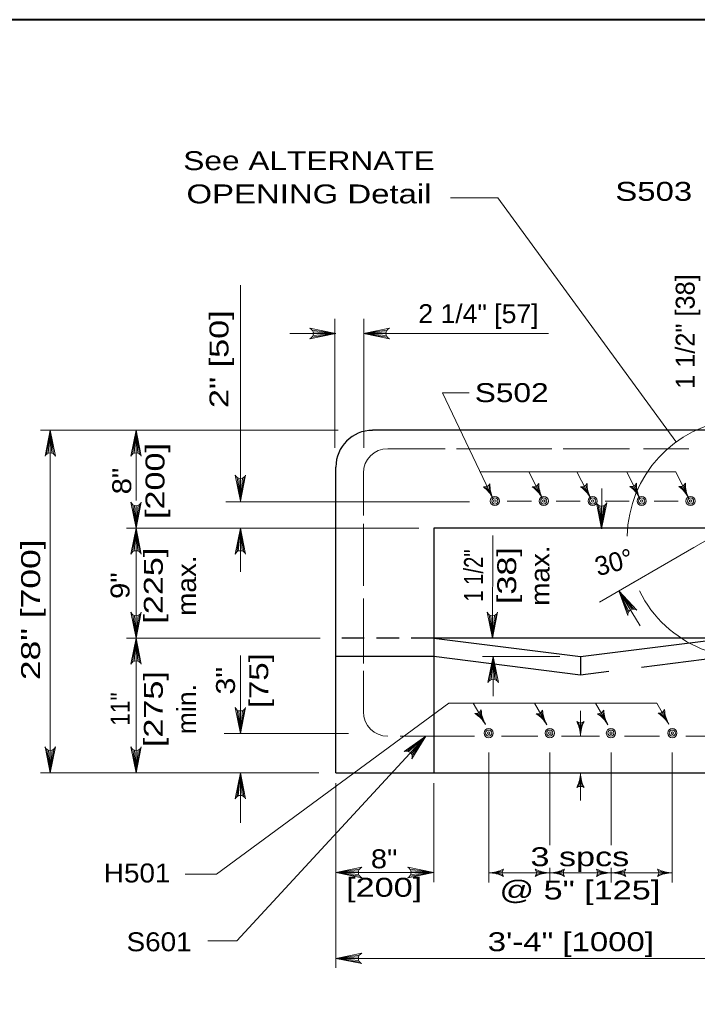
# Model space of a CAD drawing. Extents: x 758.3 to 792.3, y 849.7 to 893.7.
# Drawn here: x 775.35 to 780.94, y 863.16 to 871.19 of the extents above; entities that cross this region are included whole.
import ezdxf
from ezdxf.enums import TextEntityAlignment as Align

# ---------------------------------------------------------------- set-up
doc = ezdxf.new("R2010")
doc.units = 0
doc.header["$LTSCALE"] = 0.062
doc.linetypes.add('MEDIUM_DASHED', pattern=[4.5, 3, -1.5])
doc.layers.add('1', color=7, linetype='Continuous', lineweight=13)

msp = doc.modelspace()

# ---------------------------------------------------------------- linework, layer by layer
at = {"layer": '1', "lineweight": 25}
for p, q in [((760.3205, 871.18817), (791.8205, 871.18817)), ((781.58392, 867.80392), (778.25792, 867.80392)), ((777.95558, 864.98217), (777.95558, 867.50158)), ((781.18075, 866.99767), (778.76192, 866.99767)), ((778.76192, 865.93958), (777.95533, 865.93958)), ((779.97133, 865.78842), (778.76192, 865.93958)), ((779.97133, 865.93958), (779.97133, 865.78842)), ((781.18075, 865.93958), (780.47375, 865.85117)), ((780.20467, 865.81758), (779.97133, 865.78842)), ((777.95558, 864.98217), (781.987, 864.98217))]:
    msp.add_line(p, q, dxfattribs=at)
at = {"layer": '1'}
for p, q in [((777.16925, 867.22175), (777.16925, 868.99883)), ((777.946, 867.65858), (777.946, 868.72225)), ((778.18575, 867.65858), (778.18575, 868.72225)), ((777.76167, 868.62858), (777.95558, 868.6015)), ((777.76825, 868.61517), (777.95558, 868.6015)), ((778.37625, 868.62858), (778.18233, 868.6015)), ((778.36967, 868.61517), (778.18233, 868.6015)), ((777.57658, 868.6015), (777.95558, 868.6015)), ((777.75942, 868.5715), (777.95558, 868.6015)), ((777.76683, 868.58408), (777.95558, 868.6015)), ((777.77025, 868.6015), (777.95558, 868.6015)), ((779.70858, 868.6015), (778.18233, 868.6015)), ((778.36767, 868.6015), (778.18233, 868.6015)), ((778.37117, 868.58408), (778.18233, 868.6015)), ((778.37858, 868.5715), (778.18233, 868.6015)), ((779.25042, 867.24225), (778.83492, 868.114)), ((778.83492, 868.114), (779.05475, 868.114)), ((777.97483, 867.80392), (775.523, 867.80392)), ((775.57167, 867.60775), (775.60167, 867.80392)), ((775.58425, 867.61517), (775.60167, 867.80392)), ((775.60167, 867.61858), (775.60167, 867.80392)), ((775.61542, 867.61658), (775.60167, 867.80392)), ((775.62883, 867.61), (775.60167, 867.80392)), ((775.60167, 864.98217), (775.60167, 867.80392)), ((776.27967, 867.60767), (776.30967, 867.80392)), ((776.29225, 867.61517), (776.30967, 867.80392)), ((776.30967, 867.22517), (776.30967, 867.80392)), ((776.30967, 867.61858), (776.30967, 867.80392)), ((776.32342, 867.61658), (776.30967, 867.80392)), ((776.33683, 867.61), (776.30967, 867.80392)), ((778.85583, 867.65275), (778.38392, 867.65275)), ((779.73592, 867.65275), (778.94967, 867.65275)), ((780.37625, 867.65275), (779.82742, 867.65275)), ((780.86417, 867.65275), (780.49058, 867.65275)), ((777.14217, 867.41558), (777.16925, 867.22175)), ((777.15558, 867.409), (777.16925, 867.22175)), ((777.19925, 867.41792), (777.16925, 867.22175)), ((777.18667, 867.4105), (777.16925, 867.22175)), ((777.16925, 867.407), (777.16925, 867.22175)), ((778.18233, 867.10258), (778.18233, 867.45117)), ((780.75642, 867.46117), (779.14808, 867.46117)), ((779.657, 867.24567), (779.5445, 867.46117)), ((780.055, 867.24567), (779.9425, 867.46117)), ((780.45983, 867.24567), (780.35333, 867.46117)), ((780.863, 867.24567), (780.75642, 867.46117)), ((780.14867, 866.99333), (780.14867, 867.32417)), ((776.2825, 867.19158), (776.30967, 866.99767)), ((776.296, 867.185), (776.30967, 866.99767)), ((776.33967, 867.19383), (776.30967, 866.99767)), ((776.32708, 867.18642), (776.30967, 866.99767)), ((776.30967, 867.183), (776.30967, 866.99767)), ((779.05733, 867.21542), (777.04842, 867.21542)), ((779.36783, 867.22175), (779.567, 867.22175)), ((779.77092, 867.22175), (779.97008, 867.22175)), ((780.11833, 867.18742), (780.14542, 866.9935)), ((780.13175, 867.18083), (780.14542, 866.9935)), ((780.17542, 867.18967), (780.14542, 866.9935)), ((780.16283, 867.18225), (780.14542, 866.9935)), ((780.14542, 867.17883), (780.14542, 866.9935)), ((780.17408, 867.22175), (780.37325, 867.22175)), ((780.57725, 867.22175), (780.77642, 867.22175)), ((778.18233, 866.52325), (778.18233, 867.034)), ((778.63983, 866.99767), (776.231, 866.99767)), ((776.27967, 866.8015), (776.30967, 866.99767)), ((776.29225, 866.80892), (776.30967, 866.99767)), ((776.30967, 866.81233), (776.30967, 866.99767)), ((776.32342, 866.81033), (776.30967, 866.99767)), ((776.33683, 866.80383), (776.30967, 866.99767)), ((777.13933, 866.8015), (777.16925, 866.99767)), ((777.15183, 866.80892), (777.16925, 866.99767)), ((777.16925, 866.81233), (777.16925, 866.99767)), ((777.183, 866.81033), (777.16925, 866.99767)), ((777.19642, 866.80383), (777.16925, 866.99767)), ((777.16925, 866.63708), (777.16925, 866.99767)), ((779.2455, 866.09075), (779.24933, 866.93642)), ((781.1055, 866.95425), (780.3815, 866.53625)), ((780.9065, 866.83942), (780.12708, 866.38942)), ((780.38408, 866.32442), (780.2865, 866.482)), ((780.37108, 866.31233), (780.2865, 866.482)), ((780.36425, 866.29942), (780.2865, 866.482)), ((780.39675, 866.32992), (780.2865, 866.482)), ((780.41167, 866.33142), (780.2865, 866.482)), ((780.28717, 866.48133), (780.46225, 866.19467)), ((778.18233, 865.883), (778.18233, 866.41975)), ((776.2825, 866.28458), (776.30967, 866.09075)), ((776.33967, 866.28692), (776.30967, 866.09075)), ((779.21833, 866.28458), (779.2455, 866.09075)), ((779.2755, 866.28692), (779.2455, 866.09075)), ((776.296, 866.278), (776.30967, 866.09075)), ((776.32708, 866.2795), (776.30967, 866.09075)), ((776.30967, 866.276), (776.30967, 866.09075)), ((779.23175, 866.278), (779.2455, 866.09075)), ((779.26292, 866.2795), (779.2455, 866.09075)), ((779.2455, 866.276), (779.2455, 866.09075)), ((777.8265, 866.09075), (776.231, 866.09075)), ((776.27967, 865.8945), (776.30967, 866.09075)), ((776.29225, 865.90192), (776.30967, 866.09075)), ((776.30967, 865.90542), (776.30967, 866.09075)), ((776.32342, 865.90342), (776.30967, 866.09075)), ((776.33683, 865.89683), (776.30967, 866.09075)), ((777.16925, 865.30683), (777.16925, 865.95025)), ((779.16425, 865.93958), (779.80258, 865.93958)), ((779.222, 865.74333), (779.252, 865.93958)), ((779.23458, 865.75075), (779.252, 865.93958)), ((779.252, 865.61375), (779.252, 865.93958)), ((779.252, 865.75425), (779.252, 865.93958)), ((779.26567, 865.75225), (779.252, 865.93958)), ((779.27908, 865.74567), (779.252, 865.93958)), ((778.18233, 865.48608), (778.18233, 865.82192)), ((777.14217, 865.50075), (777.16925, 865.30683)), ((777.15558, 865.49417), (777.16925, 865.30683)), ((777.19925, 865.503), (777.16925, 865.30683)), ((777.18667, 865.49558), (777.16925, 865.30683)), ((777.16925, 865.49217), (777.16925, 865.30683)), ((779.18808, 865.38225), (779.08783, 865.55583)), ((779.69358, 865.3795), (779.59175, 865.55583)), ((779.97133, 865.2845), (779.97133, 865.49217)), ((780.19725, 865.37983), (780.09567, 865.55583)), ((780.69867, 865.38417), (780.59958, 865.55583)), ((778.05942, 865.30683), (777.0355, 865.30683)), ((778.696, 865.2845), (777.1395, 863.59783)), ((779.09925, 865.2845), (778.48433, 865.2845)), ((778.54017, 865.16158), (778.696, 865.2845)), ((778.55442, 865.15842), (778.696, 865.2845)), ((778.5695, 865.149), (778.696, 865.2845)), ((778.57817, 865.13825), (778.696, 865.2845)), ((778.58342, 865.12433), (778.696, 865.2845)), ((779.6205, 865.2845), (779.32067, 865.2845)), ((780.12792, 865.2845), (779.81433, 865.2845)), ((780.62158, 865.2845), (780.33333, 865.2845)), ((781.23192, 865.2845), (780.83842, 865.2845)), ((775.5745, 865.17608), (775.60167, 864.98217)), ((775.588, 865.1695), (775.60167, 864.98217)), ((775.63167, 865.17833), (775.60167, 864.98217)), ((775.61908, 865.17092), (775.60167, 864.98217)), ((775.60167, 865.1675), (775.60167, 864.98217)), ((776.2825, 865.17608), (776.30967, 864.98217)), ((776.296, 865.1695), (776.30967, 864.98217)), ((776.33967, 865.17833), (776.30967, 864.98217)), ((776.32708, 865.17092), (776.30967, 864.98217)), ((776.30967, 865.1675), (776.30967, 864.98217)), ((779.21542, 865.15017), (779.21542, 864.08058)), ((779.71933, 865.15017), (779.71933, 864.388)), ((780.22325, 865.15017), (780.22325, 864.388)), ((780.72717, 865.15017), (780.72717, 864.08058)), ((775.523, 864.98217), (777.81458, 864.98217)), ((777.13933, 864.786), (777.16925, 864.98217)), ((777.15183, 864.79342), (777.16925, 864.98217)), ((777.16925, 864.57042), (777.16925, 864.98217)), ((777.16925, 864.79683), (777.16925, 864.98217)), ((777.183, 864.79483), (777.16925, 864.98217)), ((777.19642, 864.78825), (777.16925, 864.98217)), ((779.97133, 864.75383), (779.97133, 864.98217)), ((777.95558, 864.89833), (777.95558, 863.37508)), ((778.76192, 864.89833), (778.76192, 864.08308)), ((777.95558, 864.17858), (777.95558, 864.52392)), ((779.71933, 864.19958), (779.71933, 864.08058)), ((780.22325, 864.19958), (780.22325, 864.08058)), ((776.97192, 864.14817), (776.71483, 864.14817)), ((778.1495, 864.18892), (777.95558, 864.16175)), ((778.14292, 864.1755), (777.95558, 864.16175)), ((777.95558, 864.16175), (778.53625, 864.16175)), ((778.14092, 864.16175), (777.95558, 864.16175)), ((778.14433, 864.14433), (777.95558, 864.16175)), ((778.15175, 864.13175), (777.95558, 864.16175)), ((778.50067, 864.16175), (778.76192, 864.16175)), ((778.56567, 864.13175), (778.76192, 864.16175)), ((778.568, 864.18892), (778.76192, 864.16175)), ((778.57317, 864.14433), (778.76192, 864.16175)), ((778.57458, 864.1755), (778.76192, 864.16175)), ((778.57658, 864.16175), (778.76192, 864.16175)), ((777.1395, 863.59783), (776.90158, 863.59783)), ((778.1495, 863.48092), (777.95558, 863.45375)), ((778.14292, 863.4675), (777.95558, 863.45375)), ((778.14092, 863.45375), (777.95558, 863.45375)), ((778.14433, 863.43633), (777.95558, 863.45375)), ((778.15175, 863.42375), (777.95558, 863.45375)), ((777.95558, 863.45375), (781.987, 863.45375))]:
    msp.add_line(p, q, dxfattribs=at)
at = {"layer": '1', "linetype": 'MEDIUM_DASHED', "lineweight": 25}
msp.add_line((778.76192, 866.09075), (777.95567, 866.09075), dxfattribs=at)
at = {"layer": '1', "lineweight": 40}
msp.add_lwpolyline([(760.3205, 871.18817), (791.8205, 871.18817), (791.8205, 850.18817), (760.3205, 850.18817)], close=True, dxfattribs=at)
at = {"layer": '1'}
for points in [[(780.75658, 867.71158), (779.28975, 869.718), (778.90092, 869.718)], [(777.74142, 868.55867), (777.95558, 868.6015), (777.74142, 868.64433)], [(778.3965, 868.55867), (778.18233, 868.6015), (778.3965, 868.64433)], [(775.55883, 867.58975), (775.60167, 867.80392), (775.6445, 867.58975)], [(776.26683, 867.58975), (776.30967, 867.80392), (776.3525, 867.58975)], [(777.21208, 867.43592), (777.16925, 867.22175), (777.12642, 867.43592)], [(776.3525, 867.21183), (776.30967, 866.99767), (776.26683, 867.21183)], [(780.18825, 867.20767), (780.14542, 866.9935), (780.10258, 867.20767)], [(776.26683, 866.7835), (776.30967, 866.99767), (776.3525, 866.7835)], [(776.30967, 864.98217), (776.30967, 866.09075), (776.30967, 866.99767)], [(777.12642, 866.7835), (777.16925, 866.99767), (777.21208, 866.7835)], [(780.36283, 866.27733), (780.2865, 866.482), (780.43567, 866.32242)], [(776.3525, 866.30492), (776.30967, 866.09075), (776.26683, 866.30492)], [(779.28833, 866.30492), (779.2455, 866.09075), (779.20267, 866.30492)], [(776.26683, 865.8765), (776.30967, 866.09075), (776.3525, 865.8765)], [(779.20917, 865.72542), (779.252, 865.93958), (779.29483, 865.72542)], [(780.59958, 865.55583), (778.88625, 865.55583), (776.97192, 864.14817)], [(777.21208, 865.521), (777.16925, 865.30683), (777.12642, 865.521)], [(778.51842, 865.15725), (778.696, 865.2845), (778.58108, 865.09875)], [(775.6445, 865.19633), (775.60167, 864.98217), (775.55883, 865.19633)], [(776.3525, 865.19633), (776.30967, 864.98217), (776.26683, 865.19633)], [(777.12642, 864.768), (777.16925, 864.98217), (777.21208, 864.768)], [(778.16975, 864.11892), (777.95558, 864.16175), (778.16975, 864.20458)], [(778.54775, 864.11892), (778.76192, 864.16175), (778.54775, 864.20458)], [(779.21542, 864.15933), (779.71933, 864.15933), (780.22325, 864.15933), (780.7275, 864.15933)], [(778.16975, 863.41092), (777.95558, 863.45375), (778.16975, 863.49658)]]:
    msp.add_lwpolyline(points, dxfattribs=at)
at = {"layer": '1', "lineweight": 25}
msp.add_lwpolyline([(778.76192, 866.99767), (778.76192, 866.177), (778.76192, 864.98217)], dxfattribs=at)
msp.add_lwpolyline([(781.18075, 866.09075), (778.76192, 866.09075), (779.97133, 865.93958)], close=True, dxfattribs=at)
at = {"layer": '1'}
for centre, start, end in [((777.72414, 868.60151), 292.08605, 67.91218), ((778.41384, 868.60151), 112.08782, 247.91395), ((775.60171, 867.57242), 22.08782, 157.91395), ((776.30971, 867.57242), 22.08782, 157.91395), ((777.16923, 867.45317), 202.08782, 337.91395), ((776.30962, 867.22915), 202.08782, 337.91395), ((780.14538, 867.22497), 202.08782, 337.91395), ((776.30971, 866.76622), 22.08782, 157.91395), ((777.16933, 866.76622), 22.08782, 157.91395), ((776.30962, 866.32218), 202.08782, 337.91395), ((779.24544, 866.32218), 202.08782, 337.91395), ((780.40838, 866.2852), 53.85151, 189.67764), ((776.30971, 865.85924), 22.08782, 157.91395), ((779.25201, 865.70808), 22.08782, 157.91395), ((777.16923, 865.53828), 202.08782, 337.91395), ((775.60162, 865.21365), 202.08782, 337.91395), ((776.30962, 865.21365), 202.08782, 337.91395), ((778.53802, 865.11531), 339.04261, 114.86874), ((777.16933, 864.75072), 22.08782, 157.91395), ((778.18707, 864.16181), 112.08782, 247.91395), ((778.53042, 864.16181), 292.08605, 67.91218), ((778.18707, 863.45382), 112.08782, 247.91395)]:
    msp.add_arc(centre, 0.04623, start, end, dxfattribs=at)
for centre, major_axis, ratio, start_param, end_param in [((781.33918, 866.91454), (0.98266, 0), 0.999895, 3.5976271, 9.4070997), ((778.38394, 867.45117), (0.20157, 0), 0.999895, 1.5707963, 3.1415926), ((779.18111, 867.38742), (0.04999, 0), 0.999895, 4.5075814, 5.8065716), ((779.01337, 867.12747), (0.26337, 0), 0.999895, 0.4510754, 0.9294319), ((779.13027, 867.18211), (0.12053, -0.23973), 0.500136, 1.5681083, 2.0065757), ((779.37252, 867.29754), (0.1103, -0.2446), 0.50014, 4.2768458, 4.712708), ((779.49373, 867.35518), (-0.26836, 0), 0.999895, 6.2484783, 6.7173096), ((779.58244, 867.38823), (0.04999, 0), 0.999895, 4.5439731, 5.8429633), ((779.42427, 867.12234), (0.26337, 0), 0.999895, 0.4874671, 0.9658237), ((779.53911, 867.18121), (-0.12918, 0.23518), 0.500133, 4.709698, 5.1481655), ((779.77699, 867.30537), (0.11913, -0.24043), 0.500137, 4.2768426, 4.7127047), ((779.89603, 867.36738), (-0.26836, 0), 0.999895, 0.0016848, 0.4705161), ((779.98045, 867.38823), (0.04999, 0), 0.999895, 4.5439731, 5.8429633), ((779.82228, 867.12234), (0.26337, 0), 0.999895, 0.4874671, 0.9658237), ((779.93711, 867.18121), (-0.12918, 0.23518), 0.500133, 4.709698, 5.1481655), ((780.175, 867.30537), (0.11913, -0.24043), 0.500137, 4.2768426, 4.7127047), ((780.29403, 867.36738), (-0.26836, 0), 0.999895, 0.0016848, 0.4705161), ((780.22448, 867.12748), (0.26337, 0), 0.999895, 0.4655355, 0.943892), ((780.38845, 867.38983), (0.04999, 0), 0.999895, 4.5220413, 5.8210315), ((780.34058, 867.18381), (-0.12399, 0.23796), 0.500135, 4.7096997, 5.1481672), ((780.58113, 867.30272), (-0.11383, 0.24298), 0.500138, 1.1352518, 1.571114), ((780.7015, 867.36211), (-0.26836, 0), 0.999895, 6.2629384, 6.7317697), ((780.79159, 867.38983), (0.04999, 0), 0.999895, 4.5220413, 5.8210315), ((780.62763, 867.12748), (0.26337, 0), 0.999895, 0.4655355, 0.943892), ((780.74373, 867.18381), (-0.12399, 0.23796), 0.500135, 4.7096997, 5.1481672), ((780.98428, 867.30272), (-0.11383, 0.24298), 0.500138, 1.1352518, 1.571114), ((781.10464, 867.36211), (-0.26836, 0), 0.999895, 6.2629384, 6.7317697), ((778.38394, 865.48606), (-0.20157, 0), 0.999895, 6.2831853, 7.8539815), ((779.10755, 865.52147), (0.04999, 0), 0.999895, 4.5868423, 5.8858325), ((779.30547, 865.44702), (0.12932, -0.2351), 0.500133, 4.2768391, 4.7127013), ((779.42174, 865.51408), (-0.26836, 0), 0.999895, 0.0445541, 0.5133854), ((779.61302, 865.51877), (0.04999, 0), 0.999895, 4.5865846, 5.8855748), ((779.81093, 865.44427), (0.12926, -0.23514), 0.500133, 4.2768392, 4.7127013), ((779.92721, 865.5113), (-0.26836, 0), 0.999895, 0.0442964, 0.5131277), ((780.11677, 865.51908), (0.04999, 0), 0.999895, 4.5864697, 5.8854599), ((780.31466, 865.44456), (0.12924, -0.23515), 0.500133, 4.2768392, 4.7127013), ((780.43095, 865.51157), (-0.26836, 0), 0.999895, 0.0441815, 0.5130128), ((780.61819, 865.52342), (0.04999, 0), 0.999895, 4.5863924, 5.8853826), ((780.81608, 865.44888), (0.12922, -0.23516), 0.500133, 4.2768392, 4.7127013), ((780.93237, 865.51589), (-0.26836, 0), 0.999895, 0.0441043, 0.5129356), ((778.96092, 865.24905), (0.26337, 0), 0.999895, 0.5303365, 1.0086931), ((779.07313, 865.31278), (-0.13914, 0.22943), 0.500129, 4.709695, 5.1481624), ((779.46632, 865.24639), (0.26337, 0), 0.999895, 0.5300788, 1.0084354), ((779.57855, 865.31009), (-0.13908, 0.22947), 0.500129, 4.7096951, 5.1481625), ((779.97122, 865.44535), (0.04999, 0), 0.999895, 4.0628939, 5.3618841), ((779.70795, 865.28282), (0.26337, 0), 0.999895, 0.006388, 0.4847446), ((779.837, 865.28187), (-0.00567, 0.26826), 0.500157, 4.7097543, 5.1482217), ((780.10534, 865.28187), (-0.00567, -0.26826), 0.500157, 4.2769014, 4.7127635), ((780.23956, 865.28177), (-0.26836, 0), 0.999895, 5.8037911, 6.2726224), ((779.97004, 865.24672), (0.26337, 0), 0.999895, 0.5299639, 1.0083205), ((780.08227, 865.31041), (0.13905, -0.22948), 0.500129, 1.5681024, 2.0065698), ((780.47144, 865.25107), (0.26337, 0), 0.999895, 0.5298867, 1.0082433), ((780.58367, 865.31475), (-0.13904, 0.22949), 0.500129, 4.7096951, 5.1481625), ((779.70308, 864.98491), (0.26836, 0), 0.999895, 5.8037911, 6.2726224), ((779.8373, 864.98481), (0.00567, 0.26826), 0.500157, 4.2769014, 4.7127635), ((780.23468, 864.98386), (-0.26337, 0), 0.999895, 0.0063881, 0.4847446), ((780.10564, 864.98481), (0.00567, -0.26826), 0.500157, 4.7097543, 5.1482217), ((779.97142, 864.82134), (-0.04999, 0), 0.999895, 4.0628942, 5.3618844), ((779.21279, 864.29367), (0.26829, 0.00567), 0.500052, 4.7097602, 5.1482277), ((779.21374, 864.4227), (0.26337, 0), 0.999895, 4.718777, 5.1971336), ((779.21279, 864.02536), (-0.26829, 0.00567), 0.500052, 4.2768954, 4.7127576), ((779.21269, 863.89115), (0.26836, 0), 0.999895, 1.0914021, 1.5602334), ((779.37628, 864.15946), (-0.04999, 0), 0.999895, 5.6336903, 6.9326805), ((779.55849, 864.15926), (0.04999, 0), 0.999895, 5.6336903, 6.9326805), ((779.72103, 863.89602), (-0.26337, 0), 0.999895, 4.718777, 5.1971336), ((779.72209, 864.42758), (-0.26836, 0), 0.999895, 1.0914021, 1.5602334), ((779.72198, 864.02505), (-0.26829, -0.00567), 0.500052, 4.7097602, 5.1482277), ((779.72198, 864.29337), (0.26829, -0.00567), 0.500052, 4.2768954, 4.7127576), ((779.71672, 864.29367), (0.26829, 0.00567), 0.500052, 4.7097602, 5.1482277), ((779.71767, 864.4227), (0.26337, 0), 0.999895, 4.718777, 5.1971336), ((779.71672, 864.02536), (-0.26829, 0.00567), 0.500052, 4.2768954, 4.7127576), ((779.71662, 863.89115), (0.26836, 0), 0.999895, 1.0914021, 1.5602334), ((779.88021, 864.15946), (-0.04999, 0), 0.999895, 5.6336903, 6.9326805), ((780.06242, 864.15926), (0.04999, 0), 0.999895, 5.6336903, 6.9326805), ((780.22496, 863.89602), (-0.26337, 0), 0.999895, 4.718777, 5.1971336), ((780.22602, 864.42758), (-0.26836, 0), 0.999895, 1.0914021, 1.5602334), ((780.22591, 864.02505), (-0.26829, -0.00567), 0.500052, 4.7097602, 5.1482277), ((780.22591, 864.29337), (0.26829, -0.00567), 0.500052, 4.2768954, 4.7127576), ((780.22065, 864.29367), (0.26829, 0.00567), 0.500052, 4.7097602, 5.1482277), ((780.2216, 864.4227), (0.26337, 0), 0.999895, 4.718777, 5.1971336), ((780.22065, 864.02536), (-0.26829, 0.00567), 0.500052, 4.2768954, 4.7127576), ((780.22055, 863.89115), (0.26836, 0), 0.999895, 1.0914021, 1.5602334), ((780.38414, 864.15946), (-0.04999, 0), 0.999895, 5.6336903, 6.9326805), ((780.56665, 864.15926), (0.04999, 0), 0.999895, 5.6336903, 6.9326805), ((780.73025, 864.42758), (-0.26836, 0), 0.999895, 1.0914021, 1.5602334), ((780.7292, 863.89602), (-0.26337, 0), 0.999895, 4.718777, 5.1971336), ((780.73015, 864.02505), (-0.26829, -0.00567), 0.500052, 4.7097602, 5.1482277), ((780.73015, 864.29337), (0.26829, -0.00567), 0.500052, 4.2768954, 4.7127576)]:
    msp.add_ellipse(centre, major_axis=major_axis, ratio=ratio, start_param=start_param, end_param=end_param, dxfattribs=at)
at = {"layer": '1', "lineweight": 25}
msp.add_ellipse((778.25796, 867.50156), major_axis=(-0.30236, 0), ratio=0.999895, start_param=4.712389, end_param=6.2831853, dxfattribs=at)
at = {"layer": '1'}
for centre, major_axis in [((779.26582, 867.22171), (0.03779, 0)), ((779.26582, 867.22171), (0.0252, 0)), ((779.66896, 867.22171), (0.03779, 0)), ((779.66896, 867.22171), (0.0252, 0)), ((780.0721, 867.22171), (0.03779, 0)), ((780.0721, 867.22171), (0.0252, 0)), ((780.47525, 867.22171), (0.03779, 0)), ((780.47525, 867.22171), (0.0252, 0)), ((780.87839, 867.22171), (0.03779, 0)), ((780.87839, 867.22171), (0.0252, 0)), ((779.26582, 867.22171), (0.01008, 0)), ((779.66896, 867.22171), (0.01008, 0)), ((780.0721, 867.22171), (0.01008, 0)), ((780.47525, 867.22171), (0.01008, 0)), ((780.87839, 867.22171), (0.01008, 0)), ((779.21512, 865.3098), (0.03779, 0)), ((779.21512, 865.3098), (0.0252, 0)), ((779.21512, 865.3098), (0.01008, 0)), ((779.71865, 865.3098), (0.03779, 0)), ((779.71865, 865.3098), (0.0252, 0)), ((779.71865, 865.3098), (0.01008, 0)), ((780.22207, 865.3098), (0.03779, 0)), ((780.22207, 865.3098), (0.0252, 0)), ((780.22207, 865.3098), (0.01008, 0)), ((780.72852, 865.3098), (0.03779, 0)), ((780.72852, 865.3098), (0.0252, 0)), ((780.72852, 865.3098), (0.01008, 0))]:
    msp.add_ellipse(centre, major_axis=major_axis, ratio=0.999895, dxfattribs=at)

# ---------------------------------------------------------------- texts
for s, width, p in [('See ALTERNATE', 1.25, (777.73438, 869.94717)), ('OPENING Detail', 1.3, (777.73442, 869.67317)), ('2 1/4" [57]', 1.05, (779.13075, 868.687)), ('8"', 1.15, (778.35337, 864.1965)), ('3 spcs', 1.35, (779.96612, 864.21375)), ('[200]', 1.35, (778.35346, 863.96183)), ('@ 5" [125]', 1.35, (779.96625, 863.93975))]:
    msp.add_text(s, height=0.156, dxfattribs=dict(at, width=width)).set_placement(p, align=Align.CENTER)
for s, width, p in [('S503', 1.3, (780.25842, 869.69442)), ('S502', 1.25, (779.10025, 868.03633)), ('H501', 1.1, (776.04383, 864.07975)), ('S601', 1.1, (776.23092, 863.51292)), ('3\'-4" [1000]', 1.3, (779.20733, 863.51342))]:
    msp.add_text(s, height=0.156, dxfattribs=dict(at, width=width)).set_placement(p)
for s, rotation, p in [('1 1/2" [38]', 90, (780.91225, 868.14525)), ('30°', 14.998, (780.11433, 866.60142))]:
    msp.add_text(s, height=0.156, rotation=rotation, dxfattribs=at).set_placement(p)
for s, width, p in [('2" [50]', 1.35, (777.0705, 867.98758)), ('28" [700]', 1.4, (775.51808, 865.74625))]:
    msp.add_text(s, height=0.156, rotation=90, dxfattribs=dict(at, width=width)).set_placement(p)
for s, width, p in [('[200]', 1.35, (776.54333, 867.38637)), ('8"', 1.15, (776.26933, 867.38629)), ('[225]', 1.35, (776.52942, 866.52454)), ('1 1/2"', 0.8, (779.16775, 866.60742)), ('[38]', 1.35, (779.44175, 866.60737)), ('max.', 1.1, (779.71575, 866.60746)), ('max.', 1.1, (776.80342, 866.52446)), ('9"', 1.15, (776.25542, 866.52454)), ('[75]', 1.3, (777.39825, 865.74167)), ('[275]', 1.35, (776.52958, 865.50746)), ('3"', 1.2, (777.12425, 865.74158)), ('min.', 1.05, (776.80358, 865.50737)), ('11"', 0.9, (776.25558, 865.50742))]:
    msp.add_text(s, height=0.156, rotation=90, dxfattribs=dict(at, width=width)).set_placement(p, align=Align.CENTER)

doc.saveas('drawing.dxf')
